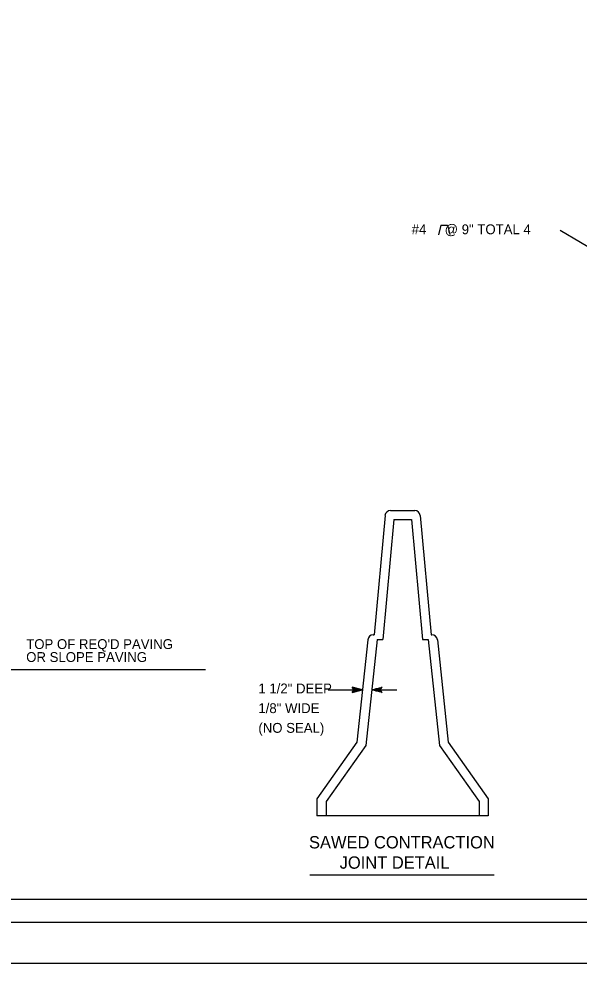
# Model space of a CAD drawing. Extents: x 504255 to 505955, y 659986 to 661086.
# Drawn here: x 504693 to 505019, y 659986 to 660536 of the extents above; entities that cross this region are included whole.
import ezdxf

# ---------------------------------------------------------------- set-up
doc = ezdxf.new("R2010")
doc.units = 0
for name, color, linetype in [('Level 62', 7, 'Continuous'), ('Level1', 7, 'Continuous'), ('Level63', 7, 'Continuous')]:
    doc.layers.add(name, color=color, linetype=linetype)

msp = doc.modelspace()

# ---------------------------------------------------------------- linework, layer by layer
at = {"layer": 'Level 62'}
msp.add_lwpolyline([(505955.48, 661086.39), (504255.48, 661086.39), (504255.48, 659986.39), (505955.48, 659986.39)], close=True, dxfattribs=at)
at = {"layer": 'Level1'}
for p, q in [((504938.72, 660416.24), (504937.22, 660410.68)), ((504938.72, 660416.24), (504942.45, 660416.24)), ((504942.45, 660416.24), (504943.94, 660410.74)), ((505033.38, 660398.1), (505008.08, 660413.22)), ((504906.12, 660247.1), (504899.73, 660177.56)), ((504911.23, 660244.72), (504904.82, 660174.93)), ((504921.48, 660244.72), (504927.89, 660174.93)), ((504926.59, 660247.1), (504932.98, 660177.56)), ((504899.27, 660177.56), (504899.73, 660177.56)), ((504932.98, 660177.56), (504933.44, 660177.56)), ((504901.47, 660174.93), (504904.82, 660174.93)), ((504927.89, 660174.93), (504931.24, 660174.93)), ((504873.05, 660145.55), (504893, 660145.55)), ((504898.35, 660145.55), (504912.95, 660145.55)), ((504862.31, 660037.73), (504969.61, 660037.73))]:
    msp.add_line(p, q, dxfattribs=at)
for points in [[(504257.9, 660010.3), (505953.07, 660010.3), (505953.07, 661062.47), (504257.9, 661062.47), (504257.9, 660010.3)], [(504327.92, 660023.67), (505946.29, 660023.67), (505946.29, 661038.56), (504327.92, 661038.56), (504327.92, 660023.67)], [(504909.29, 660249.98), (504923.42, 660249.98)], [(504911.23, 660244.72), (504921.48, 660244.72)], [(504896.1, 660174.73), (504889.76, 660115.01)], [(504901.47, 660174.93), (504894.9, 660113.1)], [(504931.24, 660174.93), (504937.81, 660113.1)], [(504936.61, 660174.73), (504942.95, 660115.01)], [(504886.96, 660144.06), (504893, 660145.55), (504886.96, 660147.05), (504887.67, 660146.56), (504888.71, 660146.56), (504887.7, 660146.06), (504890.72, 660146.06), (504888.04, 660145.55), (504890.72, 660145.06), (504887.7, 660145.06), (504888.71, 660144.56), (504887.67, 660144.56), (504886.96, 660144.06), (504887.97, 660145.55), (504886.96, 660147.05)], [(504904.39, 660144.06), (504898.35, 660145.55), (504904.39, 660147.05), (504903.68, 660146.56), (504902.64, 660146.56), (504903.65, 660146.06), (504900.63, 660146.06), (504903.31, 660145.55), (504900.63, 660145.06), (504903.65, 660145.06), (504902.64, 660144.56), (504903.68, 660144.56), (504904.39, 660144.06), (504903.38, 660145.55), (504904.39, 660147.05)], [(504889.76, 660115.01), (504866.49, 660082.09)], [(504894.9, 660113.1), (504871.8, 660080.43)], [(504937.81, 660113.1), (504960.92, 660080.43)], [(504942.95, 660115.01), (504966.23, 660082.09)], [(504866.49, 660082.09), (504866.49, 660072.22)], [(504871.8, 660080.43), (504871.8, 660072.22)], [(504960.92, 660080.43), (504960.92, 660072.22)], [(504966.23, 660082.09), (504966.23, 660072.22)], [(504966.23, 660072.22), (504866.49, 660072.22)]]:
    msp.add_lwpolyline(points, dxfattribs=at)
for centre, start_param, end_param in [((504909.29, 660246.81), 4.712389, 6.192092), ((504923.42, 660246.81), 3.232686, 4.712389), ((504899.27, 660174.4), 4.712389, 6.178514), ((504933.44, 660174.4), 3.24706, 4.712389)]:
    msp.add_ellipse(centre, major_axis=(-3.19, 0), ratio=0.99, start_param=start_param, end_param=end_param, dxfattribs=at)
at = {"layer": 'Level63'}
msp.add_line((504571.81, 660157.45), (504801.61, 660157.45), dxfattribs=at)

# ---------------------------------------------------------------- texts
at = {"layer": 'Level1'}
for s, height, p in [('#4     @ 9" TOTAL 4', 5.7391, (504921.67, 660410.95)), ("TOP OF REQ'D PAVING ", 5.7392, (504697.16, 660169.34)), ('OR SLOPE PAVING', 5.7392, (504697.16, 660161.8)), ('1 1/2" DEEP', 5.7392, (504832.37, 660143.5)), ('1/8" WIDE', 5.739, (504832.37, 660132.02)), ('(NO SEAL)', 5.739, (504832.37, 660120.54)), ('SAWED CONTRACTION', 7.1744, (504861.85, 660053.2)), ('JOINT DETAIL', 7.1744, (504879.71, 660041.38))]:
    msp.add_text(s, height=height, dxfattribs=at).set_placement(p)

doc.saveas('drawing.dxf')
